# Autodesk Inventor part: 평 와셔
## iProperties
Created: 2009-02
Part Number: 평 와셔
Material: 강, 연강
Description: 평면 와셔
Document SubType Name: Modeling
Standard: KS B 1326
Designer: SeoGD™[esajin.kr]
Standards Organization: KS
Language: ko-KR
Size Designation: 8x17
Categories: <MemberInstance><Categories><Category DisplayName="조임쇠" InternalName="e4da775c-781d-43d5-af7c-5136215cf5a6" Mnemonic="FSTN"><Category DisplayName="와셔" InternalN
Density: 1 g/cm^3
IsCustomPart: 1
Author: SeoGD™[esajin.kr]
